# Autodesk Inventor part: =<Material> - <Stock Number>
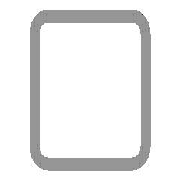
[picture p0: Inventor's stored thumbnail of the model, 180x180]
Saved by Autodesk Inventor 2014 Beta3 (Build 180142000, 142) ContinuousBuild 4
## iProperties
IsCustomPart: 1
_CCFamilyMember: 9
_CCFamilyDisplayName: ANSI AISC (Square) - Tube
_FrameMemberDoc: Frame Member File
_Version: 15.0.0
_GetPNFromCC: 1
Created: 2010-11
Part Number: =<Material> - <Stock Number>
Material: Steel, Mild
Description: Tube
Document SubType Name: Modeling
Standard: ANSI
Designer: Beta-8540w
Standards Organization: ANSI
Language: en-US
Size Designation: 3x3x3/16
Categories: <MemberInstance><Categories><Category DisplayName="Structural Shapes" InternalName="089c4875-fa83-4c05-b084-43b9cc11f5ed" Mnemonic="GRDR"><CategoryParameter Dis
Stock Number: 3x3x3/16
Density: 7.86 g/cm^3
Appearance: Steel
G_L: 16.000 in
G_W: 3.000 in
G_H: 3.000 in
Author: Beta-8540w
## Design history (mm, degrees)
node "Start plane"
node "End plane"
sketch "Sketch"
  geometry: L1 (-38.1, -28.575)-(-38.1, 28.575); L2 (-28.575, 38.1)-(28.575, 38.1); L3 (38.1, 28.575)-(38.1, -28.575); L4 (28.575, -38.1)-(-28.575, -38.1); L5 (-28.575, 33.337)-(28.575, 33.338); L6 (33.338, 28.575)-(33.338, -28.575); L7 (28.575, -33.337)-(-28.575, -33.338); L8 (-33.338, -28.575)-(-33.338, 28.575); L9 (0, 56.102)-(0, -56.102) reference; L10 (-56.102, 0)-(56.102, 0) reference; A1 r 9.525 centre (-28.575, -28.575) between (-38.1, -28.575) and (-28.575, -38.1); A2 r 9.525 centre (-28.575, 28.575) between (-28.575, 38.1) and (-38.1, 28.575); A3 r 9.525 centre (28.575, 28.575) between (38.1, 28.575) and (28.575, 38.1); A4 r 9.525 centre (28.575, -28.575) between (28.575, -38.1) and (38.1, -28.575); A5 r 4.763 centre (-28.575, 28.575) between (-28.575, 33.337) and (-33.338, 28.575); A6 r 4.763 centre (28.575, 28.575) between (33.338, 28.575) and (28.575, 33.338); A7 r 4.763 centre (28.575, -28.575) between (28.575, -33.337) and (33.338, -28.575); A8 r 4.763 centre (-28.575, -28.575) between (-33.338, -28.575) and (-28.575, -33.338)
  constraints: 16 end point, 16 point on circle, 8 centre point, 8 tangent, 4 parallel, 3 equal radius, 2 perpendicular, 7 other
  dimensions: "d10" = 76.2 distance between parallel lines of L2 L4 (= G_H); "d11" = 76.2 distance between parallel lines of L1 L3 (= G_W); "d12" = 4.7625 distance between parallel lines of L3 L6 (= G_T); "d15" = 38.1 distance between parallel lines of L2 L10 (= 0.5 x d10); "d16" = 38.1 distance between parallel lines of L9 L3 (= 0.5 x d11); "d17" = 9.525 radius of A1 (= G_IR)
extrude "Body" new body sketch "Sketch" stored distance "d3" = 406.4 (= G_L); taper "d4" = 0 deg
node "Driven Length"
  sketch "Sketch3"
    geometry: L1 (0, 0)-(10, 0) reference
    constraints: 2 end point, 1 horizontal
  workplane "Work Plane3"
  sketch "Sketch4"
    geometry: L1 (-2, -114.3)-(12, -114.3) reference; L2 (-2, 292.1)-(12, 292.1) reference
    dimensions: "d19" = 406.4 distance between parallel lines of L1 L2 (derived)
workplane "Work Plane4"
split "Split1"
body "Solid1"
other parameters: "G_W" = 76.2 [user parameter; used in 1 equation term], "G_H" = 76.2 [user parameter; used in 1 equation term], "G_T" = 4.7625 [user parameter; used in 1 equation term], "G_IR" = 9.525 [user parameter; used in 1 equation term], "G_L" = 406.4 (= d19) [user parameter; used in 1 equation term], "G_OFFSET_START" = 114.3 [user parameter; used in 1 equation term], "G_OFFSET_END" = 38.1 [user parameter; used in 1 equation term], "d13" = -114.3 (= -G_OFFSET_START), "d14" = 292.1 (= G_OFFSET_END + B_L), "B_L" = 254 [user parameter; used in 1 equation term], "d18" = 90 deg
